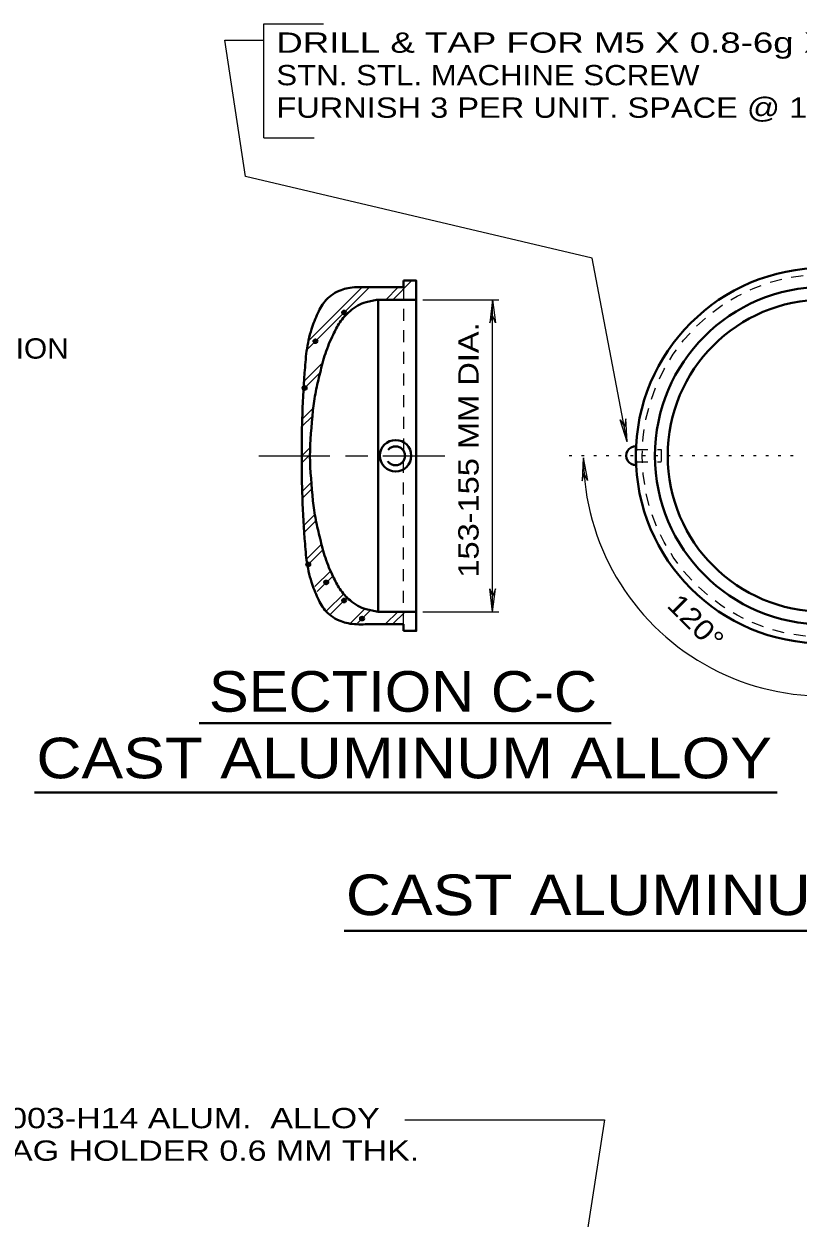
# Model space of a CAD drawing. Extents: x 312583 to 312854, y 144418 to 144597.
# Drawn here: x 312728.78 to 312757.76, y 144500.43 to 144545.14 of the extents above; entities that cross this region are included whole.
import ezdxf
from ezdxf.enums import TextEntityAlignment as Align

# ---------------------------------------------------------------- set-up
doc = ezdxf.new("R2010")
doc.units = 0
doc.header["$LTSCALE"] = 0.3
doc.header["$PDMODE"] = 32
doc.header["$PDSIZE"] = 0.15
for name, pattern in [('DOTTED', [1.5, 0.3, -1.2]), ('MEDIUM_DASHED', [4.5, 3, -1.5]), ('SHORT_DASHED', [2.7, 1.5, -1.2])]:
    doc.linetypes.add(name, pattern=pattern)
doc.layers.add('1', color=7, linetype='Continuous', lineweight=35)

msp = doc.modelspace()

# ---------------------------------------------------------------- linework, layer by layer
at = {"layer": '1', "lineweight": 13}
for p, q in [((312736.3053, 144544.5277), (312737.7616, 144544.5277)), ((312737.7616, 144540.8677), (312739.645, 144540.8677)), ((312742.5883, 144534.8134), (312743.305, 144535.5302)), ((312742.9924, 144535.4768), (312743.0382, 144535.5302)), ((312739.4239, 144532.9834), (312741.719, 144535.2862)), ((312739.462, 144533.296), (312741.414, 144535.2557)), ((312742.3214, 144534.8134), (312742.7942, 144535.2862)), ((312743.7092, 144534.8134), (312746.5609, 144534.8134)), ((312746.3245, 144534.8134), (312746.2178, 144533.9518)), ((312746.3245, 144523.1319), (312746.3245, 144534.8134)), ((312746.3245, 144534.8134), (312746.4313, 144533.9518)), ((312746.2178, 144533.9518), (312746.3245, 144534.2263)), ((312746.4313, 144533.9518), (312746.3245, 144534.2263)), ((312739.2562, 144531.7482), (312739.9424, 144532.4344)), ((312739.2485, 144531.466), (312739.8662, 144532.0913)), ((312739.218, 144530.3604), (312739.5916, 144530.7417)), ((312739.2104, 144530.0859), (312739.5535, 144530.429)), ((312751.1054, 144530.3147), (312751.2579, 144530.063)), ((312751.3646, 144529.4912), (312751.1054, 144530.3147)), ((312751.3113, 144530.3528), (312751.2579, 144530.063)), ((312751.3646, 144529.4912), (312751.3113, 144530.3528)), ((312739.1799, 144528.9727), (312739.4925, 144529.2853)), ((312737.5786, 144528.9727), (312740.2245, 144528.9727)), ((312739.1875, 144528.7058), (312739.4773, 144529.0032)), ((312740.8116, 144528.9727), (312741.658, 144528.9727)), ((312742.2146, 144528.9727), (312744.5297, 144528.9727)), ((312749.7176, 144528.8964), (312749.6719, 144528.0272)), ((312749.7176, 144528.8964), (312749.8778, 144528.0424)), ((312739.2028, 144527.6459), (312739.5383, 144527.9814)), ((312749.6719, 144528.0272), (312749.7558, 144528.3093)), ((312749.8778, 144528.0424), (312749.7558, 144528.3093)), ((312739.2104, 144527.3867), (312739.5612, 144527.7374)), ((312739.2256, 144526.3268), (312739.6984, 144526.7996)), ((312739.2409, 144526.0752), (312739.7365, 144526.5632)), ((312739.3553, 144525.0992), (312739.889, 144525.6406)), ((312739.3782, 144524.8628), (312739.9576, 144525.4347)), ((312739.6679, 144524.0698), (312740.2626, 144524.6569)), ((312739.7594, 144523.8868), (312740.3389, 144524.4663)), ((312746.2178, 144523.9936), (312746.3245, 144523.719)), ((312746.3245, 144523.1319), (312746.2178, 144523.9936)), ((312746.4313, 144523.9936), (312746.3245, 144523.719)), ((312746.3245, 144523.1319), (312746.4313, 144523.9936)), ((312740.1102, 144523.1624), (312740.7659, 144523.8182)), ((312740.2322, 144523.0099), (312740.9032, 144523.6886)), ((312741.0023, 144522.7049), (312741.5665, 144523.2692)), ((312741.2615, 144522.6973), (312741.7724, 144523.2082)), ((312742.3138, 144522.6744), (312742.7789, 144523.1319)), ((312742.5806, 144522.6668), (312743.0458, 144523.1319)), ((312743.7092, 144523.1319), (312746.5609, 144523.1319)), ((312743.4118, 144522.4152), (312743.4652, 144522.4762))]:
    msp.add_line(p, q, dxfattribs=at)
at = {"layer": '1', "lineweight": 40}
for p, q in [((312742.9924, 144535.2862), (312742.9924, 144535.5302)), ((312742.9924, 144535.2862), (312741.5589, 144535.2862)), ((312742.0393, 144534.8134), (312742.0393, 144528.9727)), ((312743.4652, 144534.8134), (312743.4652, 144528.9727)), ((312751.6849, 144528.6143), (312751.6849, 144529.3234)), ((312742.0393, 144523.1319), (312742.0393, 144528.9727)), ((312743.4652, 144523.1319), (312743.4652, 144528.9727)), ((312742.9924, 144522.6592), (312741.5589, 144522.6592)), ((312742.9924, 144522.6592), (312742.9924, 144522.4152)), ((312735.3391, 144518.9534), (312750.7682, 144518.9534)), ((312729.1763, 144516.361), (312756.9754, 144516.361)), ((312740.768, 144511.1801), (312765.8427, 144511.1801))]:
    msp.add_line(p, q, dxfattribs=at)
at = {"layer": '1', "linetype": 'SHORT_DASHED', "lineweight": 25}
for p, q in [((312742.9924, 144535.2862), (312742.9924, 144528.9727)), ((312742.9924, 144522.6592), (312742.9924, 144528.9727)), ((312751.6849, 144529.209), (312752.638, 144529.209)), ((312752.638, 144529.209), (312752.638, 144528.7363)), ((312751.6849, 144528.7363), (312752.638, 144528.7363))]:
    msp.add_line(p, q, dxfattribs=at)
at = {"layer": '1', "linetype": 'DOTTED', "lineweight": 13}
msp.add_line((312757.5714, 144528.9727), (312748.9094, 144528.9727), dxfattribs=at)
at = {"layer": '1', "lineweight": 13}
for points in [[(312737.7616, 144540.8677), (312737.7616, 144545.1377), (312739.9882, 144545.1377)], [(312751.3646, 144529.4912), (312750.0532, 144536.3689), (312737.0678, 144539.4266), (312736.3053, 144544.5277)], [(312743.0409, 144504.1076), (312750.5134, 144504.1076), (312748.8969, 144493.6537)]]:
    msp.add_lwpolyline(points, dxfattribs=at)
at = {"layer": '1', "lineweight": 40}
for points in [[(312742.0393, 144534.8134), (312743.4652, 144534.8134), (312743.4652, 144535.5302), (312742.9924, 144535.5302)], [(312742.0393, 144523.1319), (312743.4652, 144523.1319), (312743.4652, 144522.4152), (312742.9924, 144522.4152)]]:
    msp.add_lwpolyline(points, dxfattribs=at)
for centre, radius in [((312758.7171, 144528.9727), 7.0302), ((312758.7171, 144528.9727), 6.3154), ((312758.7171, 144528.9727), 5.8388), ((312742.6912, 144528.9689), 0.5897)]:
    msp.add_circle(centre, radius, dxfattribs=at)
at = {"layer": '1', "linetype": 'SHORT_DASHED', "lineweight": 25}
msp.add_circle((312758.7171, 144528.9727), 6.792, dxfattribs=at)
at = {"layer": '1', "linetype": 'MEDIUM_DASHED', "lineweight": 40}
msp.add_circle((312742.6912, 144528.9689), 0.3538, dxfattribs=at)
at = {"layer": '1', "lineweight": 40}
msp.add_arc((312751.6839, 144528.9717), 0.3555, 89.52448, 270.47552, dxfattribs=at)
at = {"layer": '1', "lineweight": 13}
msp.add_arc((312758.7171, 144528.9727), 8.996, 180.50993, 299.99393, dxfattribs=at)
at = {"layer": '1', "lineweight": 40}
for points in [[(312739.1799, 144528.9727), (312739.1952, 144530.3223), (312739.2866, 144532.0684), (312739.3629, 144532.8843), (312739.5459, 144533.7078), (312739.7823, 144534.3102), (312740.0949, 144534.8058), (312740.6515, 144535.1718), (312740.9108, 144535.248), (312741.5589, 144535.2862)], [(312742.0393, 144534.8134), (312741.8105, 144534.7677), (312741.5894, 144534.7219), (312741.2768, 144534.5923), (312740.987, 144534.3864), (312740.6058, 144533.9594), (312740.3542, 144533.5019), (312740.0644, 144532.8004), (312739.8662, 144532.076), (312739.706, 144531.3746), (312739.5993, 144530.6578), (312739.4773, 144528.9574)], [(312739.1799, 144528.9727), (312739.1952, 144527.623), (312739.2866, 144525.8769), (312739.3629, 144525.061), (312739.5459, 144524.2376), (312739.7823, 144523.6352), (312740.0949, 144523.1396), (312740.6515, 144522.7736), (312740.9108, 144522.6973), (312741.5589, 144522.6592)], [(312742.0393, 144523.1319), (312741.8105, 144523.1777), (312741.5894, 144523.2234), (312741.2768, 144523.353), (312740.987, 144523.5589), (312740.6058, 144523.9859), (312740.3542, 144524.4434), (312740.0644, 144525.1449), (312739.8662, 144525.8693), (312739.706, 144526.5708), (312739.5993, 144527.2876), (312739.4773, 144528.9574)]]:
    msp.add_spline(points, degree=3, dxfattribs=at)
at = {"layer": '1'}
for p in [(312740.7659, 144534.333), (312739.6908, 144533.2579), (312739.2866, 144531.5042), (312739.4239, 144524.9009), (312740.0949, 144524.2299), (312740.7659, 144523.5513), (312741.4369, 144522.8727)]:
    msp.add_point(p, dxfattribs=at)

# ---------------------------------------------------------------- texts
for s, width, p in [('DRILL & TAP FOR M5 X 0.8-6g X 12', 1.35, (312738.2268, 144544.0574)), ('STN. STL. MACHINE SCREW', 1.15, (312738.2268, 144542.8399)), ('FURNISH 3 PER UNIT. SPACE @ 120°', 1.2, (312738.2268, 144541.6224)), ('DEAD LOAD DEFLECTION', 1.1, (312716.6026, 144532.6064)), (' 3003-H14 ALUM.  ALLOY', 1.25, (312727.1304, 144503.7946)), (' TAG HOLDER 0.6 MM THK.', 1.25, (312727.1304, 144502.5771))]:
    msp.add_text(s, height=0.76, dxfattribs=dict(at, width=width)).set_placement(p)
for s, rotation, width, p in [('153-155 MM DIA.', 90, 1.2, (312745.7999, 144529.1855)), ('120°', 315, 1.15, (312753.6637, 144522.4787))]:
    msp.add_text(s, height=0.76, rotation=rotation, dxfattribs=dict(at, width=width)).set_placement(p, align=Align.CENTER)
for s, width, p in [('SECTION C-C', 1.1, (312742.9678, 144519.3872)), ('CAST ALUMINUM ALLOY', 1.15, (312743.0131, 144516.8945)), ('CAST ALUMINUM CAP', 1.15, (312753.2355, 144511.7726))]:
    msp.add_text(s, height=1.52, dxfattribs=dict(at, width=width)).set_placement(p, align=Align.CENTER)

doc.saveas('drawing.dxf')
